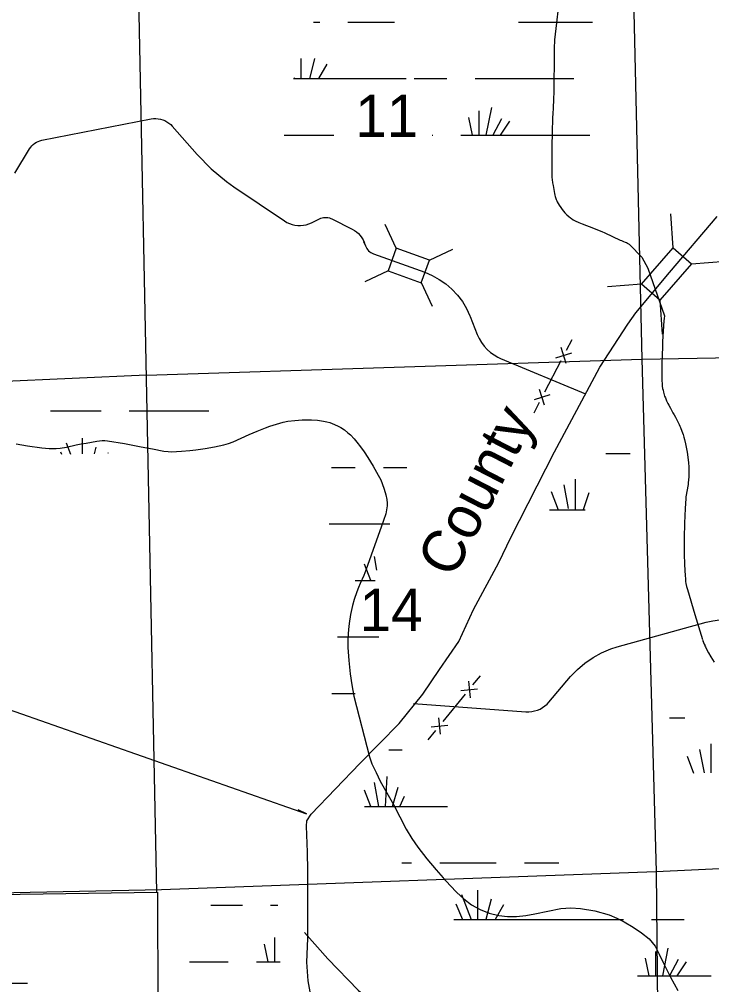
# Model space of a CAD drawing. Extents: x 2480962 to 2688785, y 277103 to 599240.
# Drawn here: x 2601822 to 2609179, y 417658 to 427912 of the extents above; entities that cross this region are included whole.
import ezdxf

# ---------------------------------------------------------------- set-up
doc = ezdxf.new("R2010")
doc.units = 0
for name, color, linetype in [('Local Roads Improved', 7, 'Continuous'), ('Local Roads Related Text', 7, 'Continuous'), ('Narrow River Creek and Branch and Slough', 7, 'Continuous'), ('Section Lines', 7, 'Continuous'), ('Section Numbers', 7, 'Continuous'), ('Swamps', 7, 'Continuous'), ('Uninventoried Roads and Features', 7, 'Continuous')]:
    doc.layers.add(name, color=color, linetype=linetype)

msp = doc.modelspace()

# ---------------------------------------------------------------- linework, layer by layer
at = {"layer": 'Local Roads Improved'}
for p, q in [((2608770.339, 425483.761), (2608744.881, 425844.903)), ((2608963.639, 425315.918), (2609324.781, 425341.376)), ((2608434.654, 425097.16), (2608073.511, 425071.703)), ((2608627.954, 424929.318), (2608653.411, 424568.175)), ((2601643.448, 420605.265), (2604873.684, 419471.226)), ((2604853.69, 418213.697), (2605099.155, 417933.135))]:
    msp.add_line(p, q, dxfattribs=at)
for points in [[(2604946.723, 417386.236), (2604891.158, 417698.792), (2604877.266, 417896.743), (2604887.685, 418150.26), (2604887.685, 418348.212), (2604887.685, 418608.674), (2604887.685, 418869.137), (2604884.212, 419067.089), (2604873.794, 419341.442), (2604877.266, 419397.008), (2604922.413, 419469.937), (2605439.866, 420008.227), (2605860.079, 420431.913), (2606110.123, 420744.468), (2606287.237, 421004.93), (2606492.135, 421303.594), (2606648.412, 421643.932), (2606915.82, 422144.02), (2607044.315, 422407.956), (2607509.675, 423317.838), (2607853.486, 423960.313), (2607988.926, 424217.303), (2608287.59, 424672.244), (2608374.411, 424793.793), (2608732.113, 425224.425), (2609235.674, 425818.28)], [(2604873.684, 419471.226), (2604786.655, 419513.999), (2604800.852, 419506.408), (2604814.177, 419497.376), (2604821.79, 419491.22)], [(2605099.155, 417933.135), (2605424.379, 417598.496), (2605673.825, 417383.92)]]:
    msp.add_lwpolyline(points, dxfattribs=at)
msp.add_lwpolyline([(2608434.654, 425097.16), (2608770.339, 425483.761), (2608963.639, 425315.918), (2608627.954, 424929.318)], close=True, dxfattribs=at)
at = {"layer": 'Narrow River Creek and Branch and Slough'}
for points in [[(2607546.797, 428029.507), (2607530.281, 427876.209), (2607516.416, 427754.829), (2607510.496, 427694.056), (2607508.257, 427663.615), (2607506.674, 427633.122), (2607505.126, 427579.021), (2607504.306, 427497.856), (2607503.891, 427416.689), (2607503.071, 427276.807), (2607501.84, 427136.929), (2607499.669, 427068.245), (2607494.026, 426965.296), (2607491.241, 426913.817), (2607489.164, 426862.313), (2607485.288, 426711.852), (2607482.076, 426561.377), (2607480.276, 426424.143), (2607479.963, 426286.895), (2607480.603, 426258.389), (2607482.114, 426233.515), (2607484.084, 426211.795), (2607488.77, 426173.86), (2607493.139, 426145.456), (2607500.693, 426102.884), (2607508.996, 426060.308), (2607512.565, 426044.358), (2607516.268, 426030.664), (2607519.958, 426018.861), (2607523.537, 426008.658), (2607526.936, 425999.816), (2607533.495, 425984.513), (2607538.931, 425973.156), (2607547.924, 425956.276), (2607557.938, 425939.531), (2607575.102, 425913.477), (2607590.91, 425891.543), (2607605.41, 425873.128), (2607618.653, 425857.692), (2607630.697, 425844.755), (2607641.602, 425833.908), (2607661.563, 425816.078), (2607677.308, 425803.745), (2607689.579, 425795.125), (2607708.76, 425783.273), (2607728.919, 425772.796), (2607767.775, 425755.266), (2607802.044, 425740.916), (2607922.771, 425694.229), (2607982.824, 425670.534), (2608012.583, 425658.009), (2608042.092, 425644.804), (2608124.486, 425606.454), (2608206.755, 425567.715), (2608219.81, 425561.952), (2608243.324, 425552.684), (2608260.892, 425545.588), (2608273.681, 425539.721), (2608282.908, 425534.817), (2608289.56, 425530.773), (2608294.373, 425527.5), (2608301.268, 425522.151), (2608307.727, 425516.211), (2608436.709, 425386.395), (2608501.05, 425270.442)], [(2608501.05, 425270.442), (2608678.289, 424763.358), (2608673.847, 424735.642), (2608671.023, 424707.99), (2608663.947, 424599.742), (2608657.676, 424491.424), (2608655.123, 424432.028), (2608652.293, 424342.923), (2608649.855, 424253.814), (2608648.809, 424201.053), (2608648.683, 424161.471), (2608649.686, 424102.093), (2608650.777, 424072.407), (2608652.294, 424042.725), (2608654.76, 424015.456), (2608658.286, 423991.756), (2608662.362, 423971.163), (2608666.647, 423953.271), (2608670.923, 423937.722), (2608679.524, 423910.777), (2608686.85, 423890.812), (2608699.135, 423861.302), (2608712.837, 423832.37), (2608722.549, 423813.559), (2608740.235, 423781.311), (2608767.403, 423733.685), (2608780.799, 423709.797), (2608793.776, 423685.609), (2608807.859, 423658.429), (2608818.254, 423638.011), (2608833.421, 423607.077), (2608840.752, 423591.374), (2608847.879, 423575.454), (2608863.28, 423537.392), (2608875.039, 423503.653), (2608884.14, 423473.834), (2608891.277, 423447.538), (2608902.126, 423401.12), (2608909.078, 423366.026), (2608917.971, 423313.035), (2608925.488, 423259.755), (2608929.156, 423229.477), (2608931.843, 423202.916), (2608935.251, 423156.35), (2608936.611, 423121.414), (2608936.899, 423095.239), (2608936.058, 423056.069), (2608933.575, 423017.069), (2608930.863, 422992.585), (2608927.684, 422971.216), (2608914.064, 422896.541), (2608908.018, 422859.085), (2608905.729, 422840.282), (2608904.137, 422821.411), (2608898.134, 422717.165), (2608891.428, 422560.732), (2608887.825, 422404.243), (2608887.412, 422334.328), (2608888.375, 422229.437), (2608891.056, 422124.55), (2608893.282, 422056.668), (2608895.929, 422005.674), (2608899.202, 421967.602), (2608902.693, 421939.238), (2608906.027, 421918.112), (2608912.371, 421886.715), (2608920.577, 421855.744), (2609000.528, 421589.518), (2609080.479, 421323.292)], [(2601787.15, 423402.813), (2601908.29, 423382.196), (2602061.682, 423360.896), (2602138.513, 423354.641), (2602176.828, 423353.626), (2602215.024, 423354.404), (2602254.724, 423357.636), (2602323.907, 423368.576), (2602427.43, 423391.176), (2602479.29, 423402.208), (2602531.346, 423411.182), (2602644.904, 423431.375), (2602701.741, 423437.612), (2602730.049, 423437.759), (2602758.236, 423435.161), (2602938.312, 423404.708), (2603118.218, 423371.097), (2603237.295, 423348.673), (2603356.466, 423326.605), (2603403.666, 423320.885), (2603439.378, 423319.46), (2603493.124, 423320.536), (2603546.686, 423323.731), (2603634.05, 423331.047), (2603699.406, 423338.401), (2603797.216, 423352.498), (2603894.823, 423370.355), (2603996.376, 423393.28), (2604046.136, 423407.806), (2604094.937, 423425.664), (2604179.226, 423463.512), (2604263.114, 423501.681), (2604349.591, 423537.62), (2604436.634, 423572.488), (2604483.141, 423589.868), (2604553.736, 423612.985), (2604626.123, 423632.941), (2604676.04, 423643.126), (2604751.258, 423651.768), (2604826.603, 423656.586), (2604883.334, 423658.404), (2604925.984, 423657.668), (2604990.002, 423652.956), (2605053.92, 423643.624), (2605089.464, 423636.025), (2605119.979, 423627.698), (2605171.913, 423609.163), (2605209.512, 423591.783), (2605236.877, 423576.695), (2605276.48, 423550.623), (2605314.21, 423520.242), (2605339.629, 423496.679), (2605380.438, 423454.227), (2605408.577, 423421.316), (2605448.013, 423370.113), (2605485.619, 423316.566), (2605525.72, 423256.309), (2605582.673, 423165.029), (2605636.385, 423070.406), (2605661.988, 423019.404), (2605678.994, 422980.545), (2605700.824, 422921.161), (2605718.058, 422860.317), (2605727.23, 422810.451), (2605730.302, 422772.181), (2605730.156, 422743.42), (2605725.547, 422700.831), (2605715.091, 422659.716), (2605666.944, 422519.103), (2605617.961, 422378.754), (2605561.835, 422219.63), (2605505.411, 422060.652), (2605482.519, 422003.116), (2605444.108, 421918.471), (2605425.16, 421875.874), (2605407.67, 421832.463), (2605379.963, 421749.539), (2605362.872, 421686.515), (2605342.378, 421590.75), (2605327.057, 421493.652), (2605319.725, 421430.295), (2605313.561, 421335.169), (2605312.941, 421287.629), (2605314.136, 421240.144), (2605323.171, 421100.366), (2605329.965, 421030.52), (2605338.496, 420960.719), (2605354.817, 420841.389), (2605364.99, 420782.232), (2605378.216, 420723.711), (2605543.335, 420078.663), (2605567.264, 420002.61)], [(2609117.93, 421235.434), (2609146.766, 421181.653), (2609169.446, 421142.064), (2609204.924, 421083.599)], [(2605567.264, 420002.61), (2605612.679, 419911.02), (2605658.094, 419819.431), (2605726.909, 419695.591), (2605798.297, 419573.136), (2605865.806, 419442.095), (2605933.4, 419310.944), (2605991.989, 419212.051), (2606057.146, 419117.222), (2606151.431, 418995.204), (2606250.11, 418876.872), (2606324.278, 418792.708), (2606399.962, 418709.87), (2606470.282, 418637.974), (2606544.228, 418569.186), (2606627.518, 418506.209), (2606719.881, 418455.29), (2606816.188, 418417.986), (2606916.054, 418394.434), (2607011.319, 418381.046), (2607106.397, 418381.005), (2607204.072, 418393.669), (2607301.533, 418409.861), (2607438.612, 418438.322), (2607575.598, 418466.104), (2607681.019, 418474.667), (2607786.886, 418468.774), (2607939.271, 418443.001), (2608088.825, 418398.698), (2608169.977, 418365.658), (2608248.145, 418326.819), (2608343.272, 418270.663), (2608434.424, 418207.779), (2608515.222, 418144.628), (2608578.689, 418067.096), (2608622.844, 417980.883), (2608665.216, 417894.015), (2608702.526, 417815.035), (2608740.996, 417736.633), (2608818.293, 417594.603)]]:
    msp.add_lwpolyline(points, dxfattribs=at)
at = {"layer": 'Section Lines'}
for p, q in [((2603282.154, 418641.555), (2602963.214, 434717.297)), ((2608316.755, 429568.554), (2608437.812, 424301.726)), ((2608437.812, 424301.726), (2613842.575, 424406.358)), ((2603173.216, 424132.27), (2608437.811, 424301.778)), ((2608437.811, 424301.778), (2608589.147, 418858.686)), ((2603173.215, 424132.31), (2597647.134, 423883.6)), ((2608589.147, 418858.686), (2613895.032, 419120.398)), ((2603334.822, 418669.249), (2608587.193, 418858.59)), ((2608589.148, 418858.674), (2608637.423, 413475.496)), ((2592487.596, 418478.733), (2603282.154, 418641.555)), ((2603307.882, 413387.756), (2603294.775, 418641.745))]:
    msp.add_line(p, q, dxfattribs=at)
at = {"layer": 'Swamps'}
for p, q in [((2604958.095, 427495.909), (2604904.486, 427281.46)), ((2605091.002, 427435.499), (2605001.284, 427281.691)), ((2606664.46, 427281.581), (2607714.465, 427281.592)), ((2606705.411, 426940.141), (2606705.415, 426681.577)), ((2606838.317, 426976.389), (2606779.379, 426681.683)), ((2606596.671, 426867.645), (2606633.883, 426681.598)), ((2606947.059, 426855.567), (2606853.053, 426680.979)), ((2607031.636, 426831.403), (2606932.317, 426682.422)), ((2602990.561, 423751.854), (2603590.564, 423751.86)), ((2607727.772, 423028.95), (2607727.777, 422702.726)), ((2607474.045, 422896.041), (2607546.542, 422702.725)), ((2607606.95, 422968.537), (2607655.283, 422714.808)), ((2605556.035, 421952.04), (2605490.561, 422123.907)), ((2605641.143, 419551.937), (2605594.887, 419806.32)), ((2605712.143, 419551.887), (2605729.379, 419867.964)), ((2605788.83, 419552.066), (2605847.062, 419755.887)), ((2605865.426, 419551.989), (2605914.31, 419660.622)), ((2606290.646, 418951.857), (2606890.649, 418951.864)), ((2608589.148, 418858.674), (2608589.148, 418858.66)), ((2597928.766, 418560.806), (2603334.822, 418669.249)), ((2606520.159, 418614.532), (2606623.181, 418351.857)), ((2606689.311, 418662.864), (2606689.316, 418351.857)), ((2606459.749, 418517.873), (2606530.563, 418351.856)), ((2606834.301, 418566.206), (2606780.691, 418351.757)), ((2606967.207, 418505.796), (2606877.489, 418351.988)), ((2606440.655, 418351.855), (2607790.663, 418351.869)), ((2607790.663, 418351.869), (2608240.665, 418351.873)), ((2604424.58, 418087.87), (2604461.792, 417901.823)), ((2604533.32, 418160.365), (2604533.324, 417901.802)), ((2608581.618, 418010.436), (2608581.622, 417751.873)), ((2608714.523, 418046.684), (2608655.586, 417751.978)), ((2603742.374, 417901.794), (2604042.375, 417901.797)), ((2608472.878, 417937.941), (2608510.09, 417751.894)), ((2608823.266, 417925.862), (2608729.26, 417751.274)), ((2608907.843, 417901.698), (2608808.524, 417752.717))]:
    msp.add_line(p, q, dxfattribs=at)
for points in [[(2604949.784, 427881.566), (2605014.444, 427881.566)], [(2605314.446, 427881.57), (2605808.214, 427881.575)], [(2607126, 427881.59), (2607912.113, 427881.599)], [(2604813.108, 427496.54), (2604813.111, 427281.56)], [(2604741.632, 427295.187), (2604746.976, 427281.559)], [(2604736.794, 427281.559), (2605914.457, 427281.572)], [(2605914.457, 427281.572), (2605931.631, 427281.573)], [(2606016.287, 427281.573), (2606364.459, 427281.577)], [(2604635.611, 426681.554), (2605164.462, 426681.56)], [(2606210.633, 426681.572), (2606214.467, 426681.572)], [(2606514.468, 426681.575), (2607884.541, 426681.59)], [(2602153.766, 423751.845), (2602690.56, 423751.851)], [(2603590.564, 423751.86), (2603836.214, 423751.863)], [(2603756.245, 423752.849), (2603754.538, 423757.313)], [(2603818.567, 423751.927), (2603818.392, 423753.052)], [(2602320.07, 423414.519), (2602367.344, 423293.982)], [(2602489.222, 423462.851), (2602489.224, 423296.108)], [(2602259.66, 423317.86), (2602270.565, 423292.295)], [(2602634.211, 423366.194), (2602617.249, 423298.34)], [(2602767.117, 423305.784), (2602764.271, 423300.903)], [(2608053.29, 423300.116), (2608313.856, 423300.119)], [(2605138.051, 423151.873), (2605390.582, 423151.876)], [(2605690.583, 423151.879), (2605939.214, 423151.881)], [(2607872.762, 422883.963), (2607812.354, 422702.727)], [(2607456.459, 422702.724), (2607835.544, 422702.728)], [(2605113.505, 422551.869), (2605758.093, 422551.876)], [(2605621.491, 422059.84), (2605594.853, 422206.336)], [(2605390.599, 421951.868), (2605603.287, 421951.87)], [(2605202.618, 421351.862), (2605642.101, 421351.866)], [(2609099.478, 421276.549), (2609104.614, 421263.16), (2609083.934, 421314.347), (2609087.841, 421304.348), (2609091.821, 421294.377), (2609094.849, 421286.921), (2609097.934, 421279.487), (2609102.622, 421268.352), (2609105.043, 421262.819), (2609107.565, 421257.331), (2609112.747, 421246.383), (2609117.93, 421235.434)], [(2605142.506, 420751.857), (2605390.616, 420751.86)], [(2608732.325, 420491.061), (2608894.685, 420491.063)], [(2609171.896, 420217.285), (2609171.9, 419907.344)], [(2605750.026, 420151.86), (2605890.627, 420151.861)], [(2609051.073, 420156.872), (2609098.692, 419906.891)], [(2608918.168, 420084.376), (2608984.993, 419906.186)], [(2605556.068, 419552.025), (2605490.595, 419723.891)], [(2605490.956, 419551.853), (2606372.121, 419551.862)], [(2605887.229, 418951.853), (2605990.644, 418951.854)], [(2607190.651, 418951.867), (2607554.043, 418951.87)], [(2603855.947, 418501.799), (2604192.368, 418501.802)], [(2604492.369, 418501.805), (2604568.23, 418501.806)], [(2608540.667, 418351.876), (2608887.243, 418351.88)], [(2603631.17, 417901.792), (2603742.374, 417901.794)], [(2604342.377, 417901.8), (2604592.859, 417901.802)], [(2600968.067, 417675.806), (2601910.792, 417675.816)], [(2608390.675, 417751.871), (2609173.445, 417751.879)]]:
    msp.add_lwpolyline(points, dxfattribs=at)
at = {"layer": 'Uninventoried Roads and Features'}
for p, q in [((2602061.886, 426627.694), (2603223.804, 426853.439)), ((2603447.336, 426777.05), (2603712.611, 426474.789)), ((2601775.987, 426277.202), (2601931.45, 426536.309)), ((2604102.133, 426132.12), (2604639.239, 425770.54)), ((2604927.014, 425751.1), (2605011.059, 425792.492)), ((2605142.836, 425791.99), (2605359.472, 425683.239)), ((2605828.042, 425482.21), (2605711.273, 425731.139)), ((2605503.684, 425503.181), (2605484.145, 425549.769)), ((2605828.042, 425482.21), (2605741.034, 425241.45)), ((2606180.718, 425354.756), (2605828.042, 425482.21)), ((2606180.718, 425354.756), (2606429.647, 425471.525)), ((2605587.384, 425421.043), (2606130.979, 425224.589)), ((2606093.71, 425113.996), (2606180.718, 425354.756)), ((2605741.034, 425241.45), (2605492.105, 425124.681)), ((2605741.034, 425241.45), (2606093.71, 425113.996)), ((2606092.904, 425115.714), (2606209.673, 424866.785)), ((2606614.256, 424754.016), (2606688.865, 424563.594)), ((2607632.258, 424255.958), (2607578.764, 424424.447)), ((2607691.757, 424506.689), (2607634.26, 424395.698)), ((2607689.755, 424366.949), (2607521.266, 424313.456)), ((2606936.568, 424310.369), (2607838.875, 423933.684)), ((2607576.762, 424284.707), (2607404.269, 423951.733)), ((2607459.765, 423922.984), (2607291.276, 423869.491)), ((2607402.267, 423811.993), (2607348.773, 423980.482)), ((2607346.771, 423840.742), (2607289.274, 423729.751)), ((2608174.283, 421245.272), (2609121.51, 421508.227)), ((2606642.241, 420841.279), (2606721.32, 420938.086)), ((2606593.838, 420880.819), (2606611.565, 420704.933)), ((2607450.22, 420659.944), (2607680.398, 420930.117)), ((2606325.923, 420454.053), (2606563.161, 420744.472)), ((2606514.758, 420784.012), (2606690.644, 420801.739)), ((2606012.125, 420644.114), (2607205.9, 420557.672)), ((2606277.52, 420493.592), (2606295.247, 420317.706)), ((2606167.765, 420260.44), (2606246.844, 420357.246)), ((2606198.441, 420396.786), (2606374.327, 420414.513))]:
    msp.add_line(p, q, dxfattribs=at)
for points in [[(2603223.804, 426853.439), (2603248.392, 426856.892), (2603273.207, 426857.756), (2603297.977, 426856.023), (2603322.429, 426851.708), (2603346.296, 426844.862), (2603369.317, 426835.558), (2603391.239, 426823.899), (2603411.824, 426810.013), (2603430.843, 426794.051), (2603447.336, 426777.05)], [(2601931.45, 426536.309), (2601942.889, 426553.291), (2601956.041, 426568.985), (2601970.761, 426583.218), (2601986.889, 426595.836), (2602004.247, 426606.697), (2602022.645, 426615.685), (2602041.882, 426622.7), (2602061.747, 426627.667), (2602061.886, 426627.694)], [(2603712.611, 426474.789), (2603859.965, 426323.637), (2604022.311, 426188.717), (2604102.133, 426132.12)], [(2604639.239, 425770.54), (2604665.067, 425755.054), (2604692.37, 425742.351), (2604720.853, 425732.572), (2604750.201, 425725.824), (2604780.095, 425722.182), (2604810.205, 425721.683), (2604840.202, 425724.335), (2604869.757, 425730.108), (2604898.548, 425738.938), (2604926.257, 425750.729), (2604927.014, 425751.1)], [(2605011.059, 425792.492), (2605025.295, 425798.599), (2605040.091, 425803.185), (2605055.285, 425806.199), (2605070.711, 425807.608), (2605086.199, 425807.398), (2605101.581, 425805.569), (2605116.687, 425802.142), (2605131.353, 425797.155), (2605142.836, 425791.99)], [(2605359.472, 425683.239), (2605383.42, 425669.603), (2605405.813, 425653.538), (2605426.402, 425635.221), (2605444.964, 425614.852), (2605461.296, 425592.654), (2605475.218, 425568.871), (2605486.577, 425543.763), (2605494.44, 425520.493)], [(2605494.44, 425520.493), (2605499.536, 425505.69), (2605506.151, 425491.5), (2605514.215, 425478.08), (2605523.636, 425465.576), (2605534.312, 425454.125), (2605546.127, 425443.853), (2605558.951, 425434.872), (2605572.644, 425427.28), (2605587.055, 425421.163), (2605587.384, 425421.043)], [(2606130.979, 425224.589), (2606209.817, 425191.336), (2606284.747, 425150.024), (2606354.948, 425101.106), (2606419.652, 425045.118), (2606478.148, 424982.673), (2606529.797, 424914.456), (2606574.033, 424841.214), (2606610.37, 424763.749), (2606614.256, 424754.016)], [(2606688.865, 424563.594), (2606708.485, 424520.335), (2606732.519, 424479.363), (2606760.703, 424441.128), (2606792.73, 424406.049), (2606828.249, 424374.509), (2606866.869, 424346.855), (2606908.169, 424323.39), (2606936.568, 424310.369)], [(2609121.51, 421508.227), (2609190.826, 421523.613), (2609261.371, 421531.67), (2609332.371, 421532.307), (2609364.837, 421530.117)], [(2607680.398, 420930.117), (2607752.383, 421006.159), (2607831.922, 421074.26), (2607918.143, 421133.673), (2608010.102, 421183.748), (2608106.792, 421223.937), (2608174.283, 421245.272)], [(2607205.9, 420557.672), (2607236.579, 420557.061), (2607267.154, 420559.659), (2607297.289, 420565.44), (2607326.656, 420574.339), (2607354.932, 420586.258), (2607381.805, 420601.069), (2607406.984, 420618.607), (2607430.192, 420638.68), (2607450.22, 420659.944)]]:
    msp.add_lwpolyline(points, dxfattribs=at)

# ---------------------------------------------------------------- texts
at = {"layer": 'Local Roads Related Text'}
msp.add_text('County', height=450, rotation=62.7204861, dxfattribs=at).set_placement((2606432.057, 421959.297))
msp.add_text('County', height=450, rotation=62.7204861, dxfattribs=at).set_placement((2606432.057, 421959.297))
at = {"layer": 'Section Numbers'}
for s, rotation, p in [('11', 0.0285639, (2605391.768, 426660.881)), ('14', 0.0285306, (2605439.144, 421413.409))]:
    msp.add_text(s, height=450, rotation=rotation, dxfattribs=at).set_placement(p)

doc.saveas('drawing.dxf')
